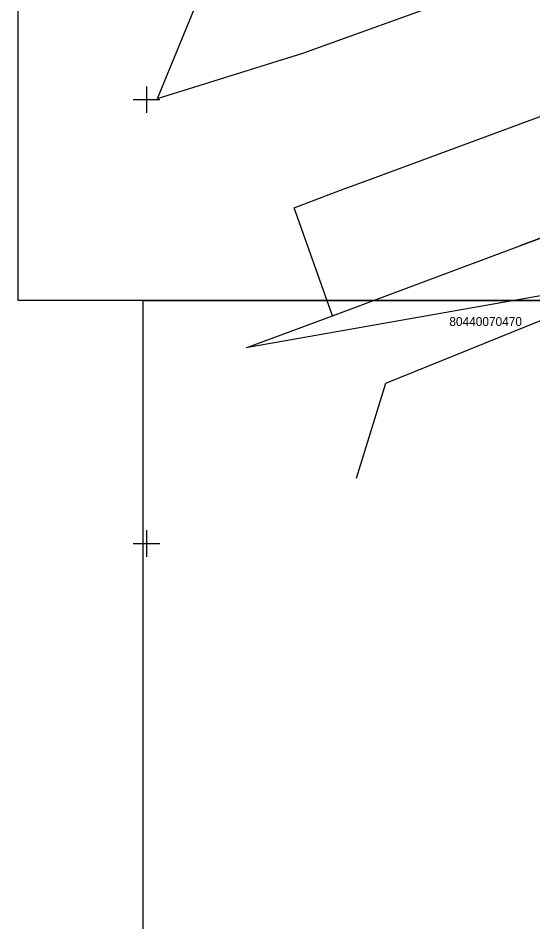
# Model space of a CAD drawing. Extents: x 519536 to 519949, y 326041 to 326519.
# Drawn here: x 519535.5 to 519593.5, y 326257.4 to 326359.2 of the extents above; entities that cross this region are included whole.
import ezdxf

# ---------------------------------------------------------------- set-up
doc = ezdxf.new("R2010")
doc.units = 0
for name, color, linetype in [('APGR_SARK_####_####_#', 7, 'Continuous'), ('GEOD_ELEM_####_####_#', 7, 'Continuous'), ('RAMI_PLAN_####_TKST_#', 7, 'Continuous'), ('ROBZ_UZMR_####_####_#', 7, 'Continuous'), ('ROBZ_UZMR_####_TKST_#', 7, 'Continuous')]:
    doc.layers.add(name, color=color, linetype=linetype)

msp = doc.modelspace()

# ---------------------------------------------------------------- linework, layer by layer
at = {"layer": 'APGR_SARK_####_####_#'}
msp.add_line((519608.06, 326339.51), (519592.05, 326333.53), dxfattribs=at)
at = {"layer": 'GEOD_ELEM_####_####_#'}
for p, q in [((519550, 326351.5), (519550, 326350)), ((519548.5, 326350), (519550, 326350)), ((519550, 326350), (519550, 326348.5)), ((519550, 326350), (519551.5, 326350)), ((519550, 326301.5), (519550, 326300)), ((519548.5, 326300), (519550, 326300)), ((519550, 326300), (519550, 326298.5)), ((519550, 326300), (519551.5, 326300))]:
    msp.add_line(p, q, dxfattribs=at)
at = {"layer": 'RAMI_PLAN_####_TKST_#'}
for p, q in [((519535.52, 326327.38), (519535.52, 326519.21)), ((519813.09, 326327.38), (519535.52, 326327.38)), ((519549.62, 326327.38), (519948.98, 326327.38)), ((519549.62, 326040.52), (519549.62, 326327.38))]:
    msp.add_line(p, q, dxfattribs=at)
at = {"layer": 'ROBZ_UZMR_####_####_#'}
for p, q in [((519559.01, 326369.12), (519551.21, 326350.08)), ((519594.88, 326365.05), (519567.58, 326355.2)), ((519567.58, 326355.2), (519551.21, 326350.08)), ((519574.75, 326340.84), (519595.66, 326348.58)), ((519572.14, 326339.91), (519574.75, 326340.84)), ((519566.62, 326337.82), (519572.14, 326339.91)), ((519592.05, 326333.53), (519608.06, 326339.51)), ((519570.95, 326325.66), (519566.62, 326337.82)), ((519570.95, 326325.66), (519592.05, 326333.53)), ((519561.43, 326322.12), (519606.9, 326330.17)), ((519576.95, 326318.08), (519606.9, 326330.17)), ((519561.43, 326322.12), (519570.95, 326325.66)), ((519561.21, 326322.08), (519561.43, 326322.12)), ((519573.65, 326307.35), (519576.95, 326318.08))]:
    msp.add_line(p, q, dxfattribs=at)

# ---------------------------------------------------------------- texts
at = {"layer": 'ROBZ_UZMR_####_TKST_#'}
msp.add_text('80440070470', height=1, dxfattribs=at).set_placement((519584.12, 326324.51))

doc.saveas('drawing.dxf')
